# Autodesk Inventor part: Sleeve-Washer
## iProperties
Company: Autodesk, Inc.
Shininess: 64.0
Length Units: 11269
Angle Units: 11279
Time Units: 11290
Mass Units: 11283
Length Display Precision: 3
Angle Display Precision: 2
Compacted: True
Part Number: Sleeve-Washer
Document SubType Name: Modeling
Created: 2003-12
Catalog Web Link: www.autodesk.com
Vendor: Autodesk, Inc.
Designer: Administrator
Manufacturer: Standard
Standards Organization: Custom
Density: 1 g/cm^3
Density: 0.0
Volumn: 0.0
Area: 0.0
PropertySet Name: Model Information
Control State: 0
Master: False
Checked Out: False
Author: Administrator
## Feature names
1. Extrusion1
2. Extrusion2
